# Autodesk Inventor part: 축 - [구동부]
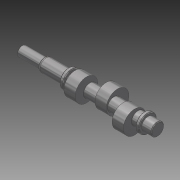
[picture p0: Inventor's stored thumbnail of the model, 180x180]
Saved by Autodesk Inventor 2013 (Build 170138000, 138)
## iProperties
Company: 한국ATC센터
Created: 2014-08
Part Number: 축 - [구동부]
Document SubType Name: Modeling
Designer: mdu
Density: 7.86 g/cm^3
Material: 강철, 연강
Mass: 484.347 g
Surface Area: 153.549 cm^2
Volume: 61.6218 cm^3
Author: mdu
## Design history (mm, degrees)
sketch "스케치1"
  geometry: L1 (-90.5, 0)-(90.5, 0); L2 (-90.5, 0)-(-90.5, 6.5); L3 (-58.681, 8.5)-(-28.5, 8.5); L4 (-28.5, 8.5)-(-28.5, 12); L5 (-28.5, 12)-(-23.5, 12); L6 (-23.5, 12)-(-23.5, 8.5); L7 (-23.5, 8.5)-(72.5, 8.5); L8 (72.5, 8.5)-(72.5, 12); L9 (72.5, 12)-(77.5, 12); L10 (77.5, 12)-(77.5, 8.5); L11 (77.5, 8.5)-(90.5, 8.5); L12 (90.5, 8.5)-(90.5, 0); L13 (-60.5, 7.45)-(-60.5, 6.5); L14 (-60.5, 6.5)-(-90.5, 6.5); L15 (-60.5, 7.45)-(-58.681, 8.5); 2 further points
  constraints: 30 end point, 6 parallel, 2 perpendicular, 1 coincident, 1 horizontal, 1 midpoint
  dimensions: "d0" = 181 distance of L1.start L1.end (derived); "d2" = 17 diameter of L3 L1; "d3" = 24 diameter of L5 L1; "d4" = 17 diameter of L7 L1; "d5" = 24 diameter of L9 L1; "d6" = 17 diameter of L11 L1; "d7" = 5 distance of L8.end L9.end; "d8" = 5 distance of L4.end L5.end; "d11" = 13 distance of L10.end L11.end; "d35" = 96 distance between parallel lines of L8 L6; "d57" = 13 diameter of L14 L1; "d58" = 62 distance between parallel lines of L4 L2; "d60" = 30 horizontal distance of L2.end L13.start; "d61" = 14.9 diameter of L13.start L1; "d62" = 30 deg angle of L3 L15
revolve "회전1" sketch "스케치1" stored, may be unused: angle "d12" = 90 deg
node "작업 평면7"
sketch "스케치6"
  geometry: C1 r 15 at (0, 5); 1 further point
  constraints: 1 centre point, 1 vertical alignment
  dimensions: "d37" = 30 diameter of C1; "d38" = 5 distance of C1.centre point (0, 0)
extrude "돌출4" join sketch "스케치6" stored distance "d33" = 15; taper "d34" = 0 deg
node "작업 평면8"
sketch "스케치7"
  geometry: L1 (0, 0)-(-6, -10.392); L2 (0, 0)-(12, 0); C1 r 15 at (-2.5, -4.33); A1 r 12 centre (0, 0) between (-6, -10.392) and (12, 0) reference; 1 further point
  constraints: 4 end point, 2 point on circle, 1 centre point, 1 horizontal, 1 point on line
  dimensions: "d40" = 120 deg angle of L1 L2; "d41" = 30 diameter of C1; "d42" = 5 distance of point (0, 0) C1.centre
extrude "돌출5" join sketch "스케치7" stored distance "d43" = 15; taper "d44" = 0 deg
node "작업 평면9"
sketch "스케치8"
  geometry: L1 (0, 0)-(4.25, -7.361); L2 (0, 0)-(-8.5, 0); C1 r 15 at (2.5, -4.33); A1 r 8.5 centre (0, 0) between (4.25, -7.361) and (-8.5, 0) reference; 1 further point
  constraints: 4 end point, 2 point on circle, 1 centre point, 1 horizontal, 1 point on line
  dimensions: "d46" = 120 deg angle of L1 L2; "d47" = 30 diameter of C1; "d48" = 5 distance of point (0, 0) C1.centre
extrude "돌출6" join sketch "스케치8" stored distance "d49" = 15; taper "d50" = 0 deg
node "작업 평면3"
sketch "스케치5"
  geometry: L1 (84, -2.5)-(71, -2.5); L2 (71, 2.5)-(84, 2.5); L3 (60.5, 7.45)-(60.5, -7.45) reference; A1 r 2.5 centre (71, 0) between (71, 2.5) and (71, -2.5); A2 r 2.5 centre (84, 0) between (84, -2.5) and (84, 2.5); 2 further points
  constraints: 4 end point, 4 point on circle, 4 tangent, 3 horizontal alignment, 2 centre point, 1 midpoint, 1 parallel
  dimensions: "d23" = 5 distance between parallel lines of L2 L1; "d67" = 18 dimension on A2 A1; "d68" = 8 distance edge to line of A1 L3
extrude "돌출3" cut sketch "스케치5" distance "d25" = 3; taper "d26" = 0 deg
chamfer "모따기1" distance "d27" = 1; stored, may be unused: second distance "d28" = 2, angle "d29" = 45 deg
fillet "모깎기1" dims "d51" = 0.3
chamfer "모따기2" distance "d53" = 1; stored, may be unused: second distance "d54" = 2, angle "d55" = 45 deg
node "작업 평면10"
fillet "모깎기2" dims "d63" = 4
fillet "모깎기3" dims "d64" = 1
node "솔리드1"
other parameters: "d39" = -32, "d45" = 32, "d66" = 6.5
